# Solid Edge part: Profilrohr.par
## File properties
Username: bmolnar
Dokumentum tartalom típus: 0
Author: bmolnar
Last saved by: bmolnar
Revision: 88
Sűrűség: 0,000 kg/m^3
Pontosság: 0,990
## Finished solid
Body 1: solid body, 63 faces, 178 edges, 112 vertices.
  Faces by surface: cylinder 33, plane 30
  Edges by curve: line 112, circle 66
Bounding box of the edges (mm): 36.000 x 93.400 x 36.000, from (-18, -84.15, -18) to (18, 9.25, 18).
Cylindrical faces by radius (mm): R0.2 x12, R0.5 x12, R3.775 x4, R4.5 x4, R10 x1
Planar faces by outward normal: +x 7, +y 1, +z 7, -x 7, -y 1, -z 7
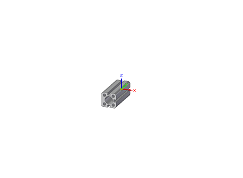
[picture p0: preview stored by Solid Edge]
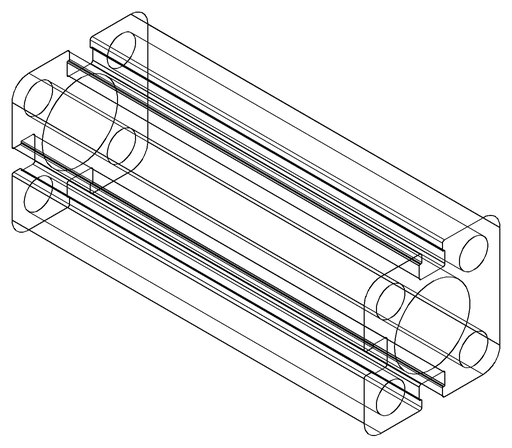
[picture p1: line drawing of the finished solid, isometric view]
